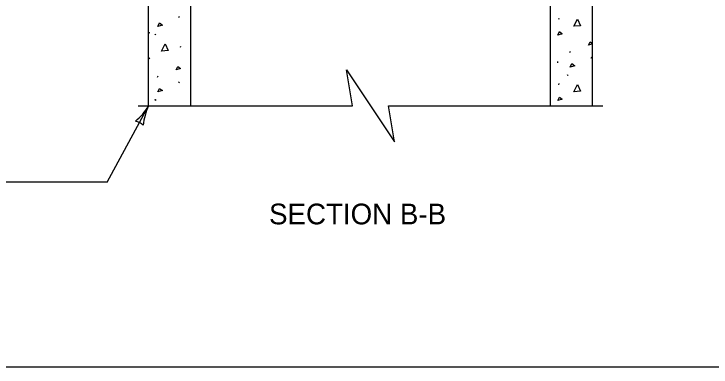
# Model space of a CAD drawing. Extents: x 49991.4 to 50048.3, y 49987.6 to 50018.3.
# Drawn here: x 50007.217 to 50009.908, y 49987.799 to 49989.162 of the extents above; entities that cross this region are included whole.
import ezdxf

# ---------------------------------------------------------------- set-up
doc = ezdxf.new("R2010")
doc.units = 0
for name, color, linetype in [('Level 1', 7, 'Continuous'), ('Level 2', 7, 'Continuous'), ('Level 3', 7, 'Continuous'), ('Level 6', 7, 'Continuous')]:
    doc.layers.add(name, color=color, linetype=linetype)

msp = doc.modelspace()

# ---------------------------------------------------------------- linework, layer by layer
at = {"layer": 'Level 1'}
for p, q in [((50009.2884, 49988.8071), (50009.2884, 49990.0374)), ((50009.4509, 49988.8071), (50009.4509, 49990.0374)), ((50007.7369, 49988.8071), (50007.7369, 49989.8519)), ((50007.8993, 49988.8071), (50007.8993, 49989.8519)), ((50007.8539, 49989.1487), (50007.8561, 49989.1536)), ((50009.3203, 49989.1416), (50009.3225, 49989.1464)), ((50007.7369, 49989.0846), (50007.7405, 49989.0937)), ((50007.7602, 49989.0859), (50007.7624, 49989.0827)), ((50007.7624, 49989.0847), (50007.7646, 49989.0815)), ((50009.4509, 49989.0466), (50009.4352, 49989.0417)), ((50007.8593, 49989.0334), (50007.8615, 49989.0382)), ((50009.3636, 49989.0138), (50009.3658, 49989.0187)), ((50009.4459, 49988.9916), (50009.4481, 49988.9965)), ((50009.3153, 49988.978), (50009.3159, 49988.9732)), ((50007.7716, 49988.9181), (50007.7738, 49988.9229)), ((50009.3523, 49988.9288), (50009.3544, 49988.9256)), ((50009.3544, 49988.9276), (50009.3566, 49988.9243)), ((50007.8539, 49988.8959), (50007.8561, 49988.9007)), ((50009.3203, 49988.8887), (50009.3225, 49988.8936)), ((50007.7602, 49988.8331), (50007.7624, 49988.8298)), ((50007.7624, 49988.8318), (50007.7646, 49988.8286))]:
    msp.add_line(p, q, dxfattribs=at)
msp.add_lwpolyline([(49999.3835, 49998.9992), (50016.7501, 49998.9992), (50016.7501, 49987.7988), (49999.3835, 49987.7988)], close=True, dxfattribs=at)
for points in [[(50007.7727, 49989.1141), (50007.7792, 49989.1276), (50007.79, 49989.1195), (50007.7727, 49989.1141)], [(50009.3783, 49989.1145), (50009.3929, 49989.1421), (50009.4043, 49989.1167), (50009.3788, 49989.1145)], [(50009.3165, 49989.0804), (50009.323, 49989.0939), (50009.3339, 49989.0858), (50009.3165, 49989.0804)], [(50007.7862, 49989.0187), (50007.8008, 49989.0464), (50007.8122, 49989.0209), (50007.7868, 49989.0187)], [(50009.4352, 49989.0417), (50009.4417, 49989.0552), (50009.4509, 49989.0483)], [(50007.7369, 49988.9938), (50007.7418, 49988.9901), (50007.7369, 49988.9885)], [(50009.3647, 49988.957), (50009.3712, 49988.9705), (50009.3821, 49988.9624), (50009.3647, 49988.957)], [(50007.8432, 49988.9459), (50007.8497, 49988.9595), (50007.8605, 49988.9514), (50007.8432, 49988.9459)], [(50009.3783, 49988.8616), (50009.3929, 49988.8892), (50009.4043, 49988.8638), (50009.3788, 49988.8616)], [(50007.7727, 49988.8612), (50007.7792, 49988.8748), (50007.79, 49988.8666), (50007.7727, 49988.8612)], [(50009.3165, 49988.8275), (50009.323, 49988.8411), (50009.3339, 49988.8329), (50009.3165, 49988.8275)]]:
    msp.add_lwpolyline(points, dxfattribs=at)
at = {"layer": 'Level 3'}
for q in [(50007.7369, 49988.8071), (50006.8068, 49988.5133)]:
    msp.add_line((50007.5773, 49988.5133), q, dxfattribs=at)
for centre, radius, start, end in [((50007.546, 49988.9211), 0.2223, 308.9548, 329.1383), ((50007.9469, 49988.7061), 0.233, 154.3261, 173.5759), ((50007.6757, 49988.6944), 0.0548, 43.6376, 79.3599)]:
    msp.add_arc(centre, radius, start, end, dxfattribs=at)
at = {"layer": 'Level 6'}
msp.add_lwpolyline([(50007.6969, 49988.8071), (50008.5243, 49988.8071), (50008.5012, 49988.9462), (50008.6866, 49988.668), (50008.6634, 49988.8071), (50009.4909, 49988.8071)], dxfattribs=at)

# ---------------------------------------------------------------- texts
at = {"layer": 'Level 2'}
msp.add_text('SECTION B-B', height=0.08, dxfattribs=at).set_placement((50008.2018, 49988.3498))

doc.saveas('drawing.dxf')
